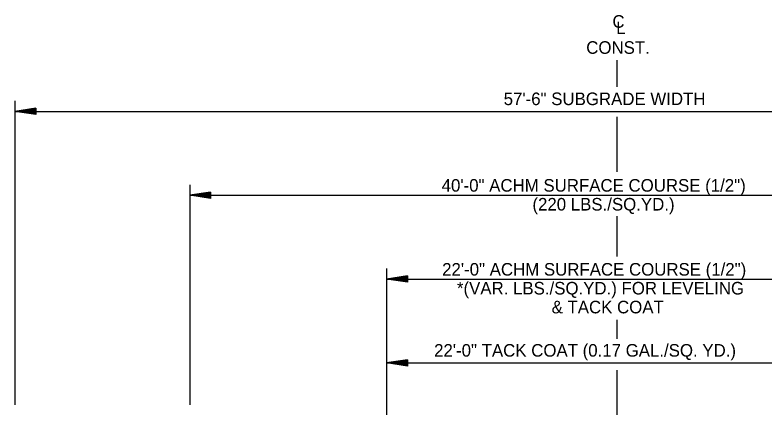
# Model space of a CAD drawing. Extents: x 2263886 to 2266026, y -3122850 to -3121850.
# Drawn here: x 2265570.89 to 2265606.6, y -3122391.11 to -3122372.4 of the extents above; entities that cross this region are included whole.
import ezdxf

# ---------------------------------------------------------------- set-up
doc = ezdxf.new("R2010")
doc.units = 0
doc.layers.add('R_Border Prem', color=7, linetype='Continuous')

msp = doc.modelspace()

# ---------------------------------------------------------------- linework, layer by layer
at = {"layer": 'R_Border Prem'}
for p, q in [((2265599.599, -3122375.825), (2265599.599, -3122374.566)), ((2265570.889, -3122376.506), (2265570.889, -3122391.003)), ((2265571.889, -3122376.853), (2265570.889, -3122377.003)), ((2265571.889, -3122376.878), (2265571.056, -3122377.003)), ((2265571.889, -3122376.904), (2265571.228, -3122377.003)), ((2265571.889, -3122376.929), (2265571.395, -3122377.003)), ((2265571.889, -3122376.853), (2265571.889, -3122377.153)), ((2265570.889, -3122377.003), (2265628.309, -3122377.003)), ((2265571.889, -3122377.153), (2265570.889, -3122377.003)), ((2265571.889, -3122377.128), (2265571.056, -3122377.003)), ((2265571.889, -3122377.103), (2265571.228, -3122377.003)), ((2265571.889, -3122377.078), (2265571.395, -3122377.003)), ((2265571.889, -3122376.955), (2265571.564, -3122377.003)), ((2265571.889, -3122377.052), (2265571.564, -3122377.003)), ((2265571.889, -3122376.98), (2265571.731, -3122377.003)), ((2265571.889, -3122377.027), (2265571.731, -3122377.003)), ((2265599.599, -3122379.893), (2265599.599, -3122377.256)), ((2265579.219, -3122380.503), (2265579.219, -3122391.003)), ((2265580.219, -3122380.853), (2265579.219, -3122381.003)), ((2265580.219, -3122380.878), (2265579.386, -3122381.003)), ((2265580.219, -3122380.853), (2265580.219, -3122381.153)), ((2265580.219, -3122381.153), (2265579.219, -3122381.003)), ((2265579.219, -3122381.003), (2265619.979, -3122381.003)), ((2265580.219, -3122381.128), (2265579.386, -3122381.003)), ((2265580.219, -3122380.904), (2265579.558, -3122381.003)), ((2265580.219, -3122381.103), (2265579.558, -3122381.003)), ((2265580.219, -3122380.929), (2265579.724, -3122381.003)), ((2265580.219, -3122381.078), (2265579.724, -3122381.003)), ((2265580.219, -3122380.955), (2265579.894, -3122381.003)), ((2265580.219, -3122381.052), (2265579.894, -3122381.003)), ((2265580.219, -3122380.98), (2265580.061, -3122381.003)), ((2265580.219, -3122381.027), (2265580.061, -3122381.003)), ((2265599.599, -3122383.932), (2265599.599, -3122382.008)), ((2265588.602, -3122384.503), (2265588.602, -3122402.224)), ((2265589.602, -3122384.853), (2265588.602, -3122385.003)), ((2265588.602, -3122385.003), (2265610.596, -3122385.003)), ((2265589.602, -3122385.153), (2265588.602, -3122385.003)), ((2265589.602, -3122384.878), (2265588.769, -3122385.003)), ((2265589.602, -3122385.128), (2265588.769, -3122385.003)), ((2265589.602, -3122384.904), (2265588.941, -3122385.003)), ((2265589.602, -3122385.103), (2265588.941, -3122385.003)), ((2265589.602, -3122384.929), (2265589.108, -3122385.003)), ((2265589.602, -3122385.078), (2265589.108, -3122385.003)), ((2265589.602, -3122384.955), (2265589.277, -3122385.003)), ((2265589.602, -3122385.052), (2265589.277, -3122385.003)), ((2265589.602, -3122384.98), (2265589.444, -3122385.003)), ((2265589.602, -3122385.027), (2265589.444, -3122385.003)), ((2265589.602, -3122384.853), (2265589.602, -3122385.153)), ((2265599.599, -3122387.856), (2265599.599, -3122386.945)), ((2265589.602, -3122388.853), (2265588.602, -3122389.003)), ((2265588.602, -3122389.003), (2265610.596, -3122389.003)), ((2265589.602, -3122389.153), (2265588.602, -3122389.003)), ((2265589.602, -3122388.878), (2265588.769, -3122389.003)), ((2265589.602, -3122389.128), (2265588.769, -3122389.003)), ((2265589.602, -3122388.904), (2265588.941, -3122389.003)), ((2265589.602, -3122389.103), (2265588.941, -3122389.003)), ((2265589.602, -3122388.929), (2265589.108, -3122389.003)), ((2265589.602, -3122389.078), (2265589.108, -3122389.003)), ((2265589.602, -3122388.955), (2265589.277, -3122389.003)), ((2265589.602, -3122389.052), (2265589.277, -3122389.003)), ((2265589.602, -3122388.98), (2265589.444, -3122389.003)), ((2265589.602, -3122389.027), (2265589.444, -3122389.003)), ((2265589.602, -3122388.853), (2265589.602, -3122389.153)), ((2265599.599, -3122402.224), (2265599.599, -3122389.346))]:
    msp.add_line(p, q, dxfattribs=at)

# ---------------------------------------------------------------- texts
for s, p in [('C', (2265599.374, -3122373.012)), ('L', (2265599.555, -3122373.317)), ('CONST.', (2265598.126, -3122374.256))]:
    msp.add_text(s, height=0.6, dxfattribs=at).set_placement(p)
for s, p in [('57\'-6" SUBGRADE WIDTH', (2265594.19, -3122376.703)), ('40\'-0" ACHM SURFACE COURSE (1/2")', (2265591.232, -3122380.832)), ('(220 LBS./SQ.YD.)', (2265595.56, -3122381.732)), ('22\'-0" ACHM SURFACE COURSE (1/2")', (2265591.256, -3122384.837)), ('*(VAR. LBS./SQ.YD.) FOR LEVELING', (2265591.962, -3122385.737)), ('& TACK COAT', (2265596.474, -3122386.637)), ('22\'-0" TACK COAT (0.17 GAL./SQ. YD.)', (2265590.873, -3122388.703))]:
    msp.add_text(s, height=0.6, rotation=360, dxfattribs=at).set_placement(p)

doc.saveas('drawing.dxf')
